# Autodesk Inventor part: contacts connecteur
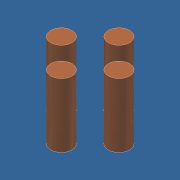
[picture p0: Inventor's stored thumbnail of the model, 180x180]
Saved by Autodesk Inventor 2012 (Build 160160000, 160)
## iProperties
Created: 2011-10
Part Number: contacts connecteur
Material: Cuivre
Document SubType Name: Modeling
Designer: Laur
Mass: 0.0842575 g
Surface Area: 0.439823 cm^2
Volume: 0.00942478 cm^3
Density: 8.94 g/cm^3
Author: Laur
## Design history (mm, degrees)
sketch "Esquisse1"
  geometry: L1 (4.806, 0.4)-(3.456, 0.4); L2 (4.806, 0.4)-(6.156, 0.4); L3 (4.806, 0.4)-(4.806, 1.75); L4 (4.806, 0.4)-(4.806, -0.95); C1 r 0.5 at (4.806, 1.75); C2 r 0.5 at (3.456, 0.4); C3 r 0.5 at (4.806, -0.95); C4 r 0.5 at (6.156, 0.4); C5 r 3.15 at (4.806, 0.4) reference; A1 r 1.35 centre (4.806, 0.4) between (4.806, 1.75) and (3.456, 0.4); 1 further point
  constraints: 8 end point, 5 centre point, 5 coincident, 4 point on circle, 2 collinear, 2 point on line, 1 perpendicular, 1 vertical
  dimensions: "d0" = 1 diameter of C1; "d1" = 1 diameter of C2 (= d0); "d2" = 1 diameter of C3 (= d0); "d3" = 1 diameter of C4 (= d0); "d4" = 2.7 diameter of A1
extrude "Extrusion1" new body sketch "Esquisse1" distance "d5" = 3; taper "d6" = 0 deg
node "Solide1"
node "Corps solides"
node "Corps surfaciques"
node "Référence2"
